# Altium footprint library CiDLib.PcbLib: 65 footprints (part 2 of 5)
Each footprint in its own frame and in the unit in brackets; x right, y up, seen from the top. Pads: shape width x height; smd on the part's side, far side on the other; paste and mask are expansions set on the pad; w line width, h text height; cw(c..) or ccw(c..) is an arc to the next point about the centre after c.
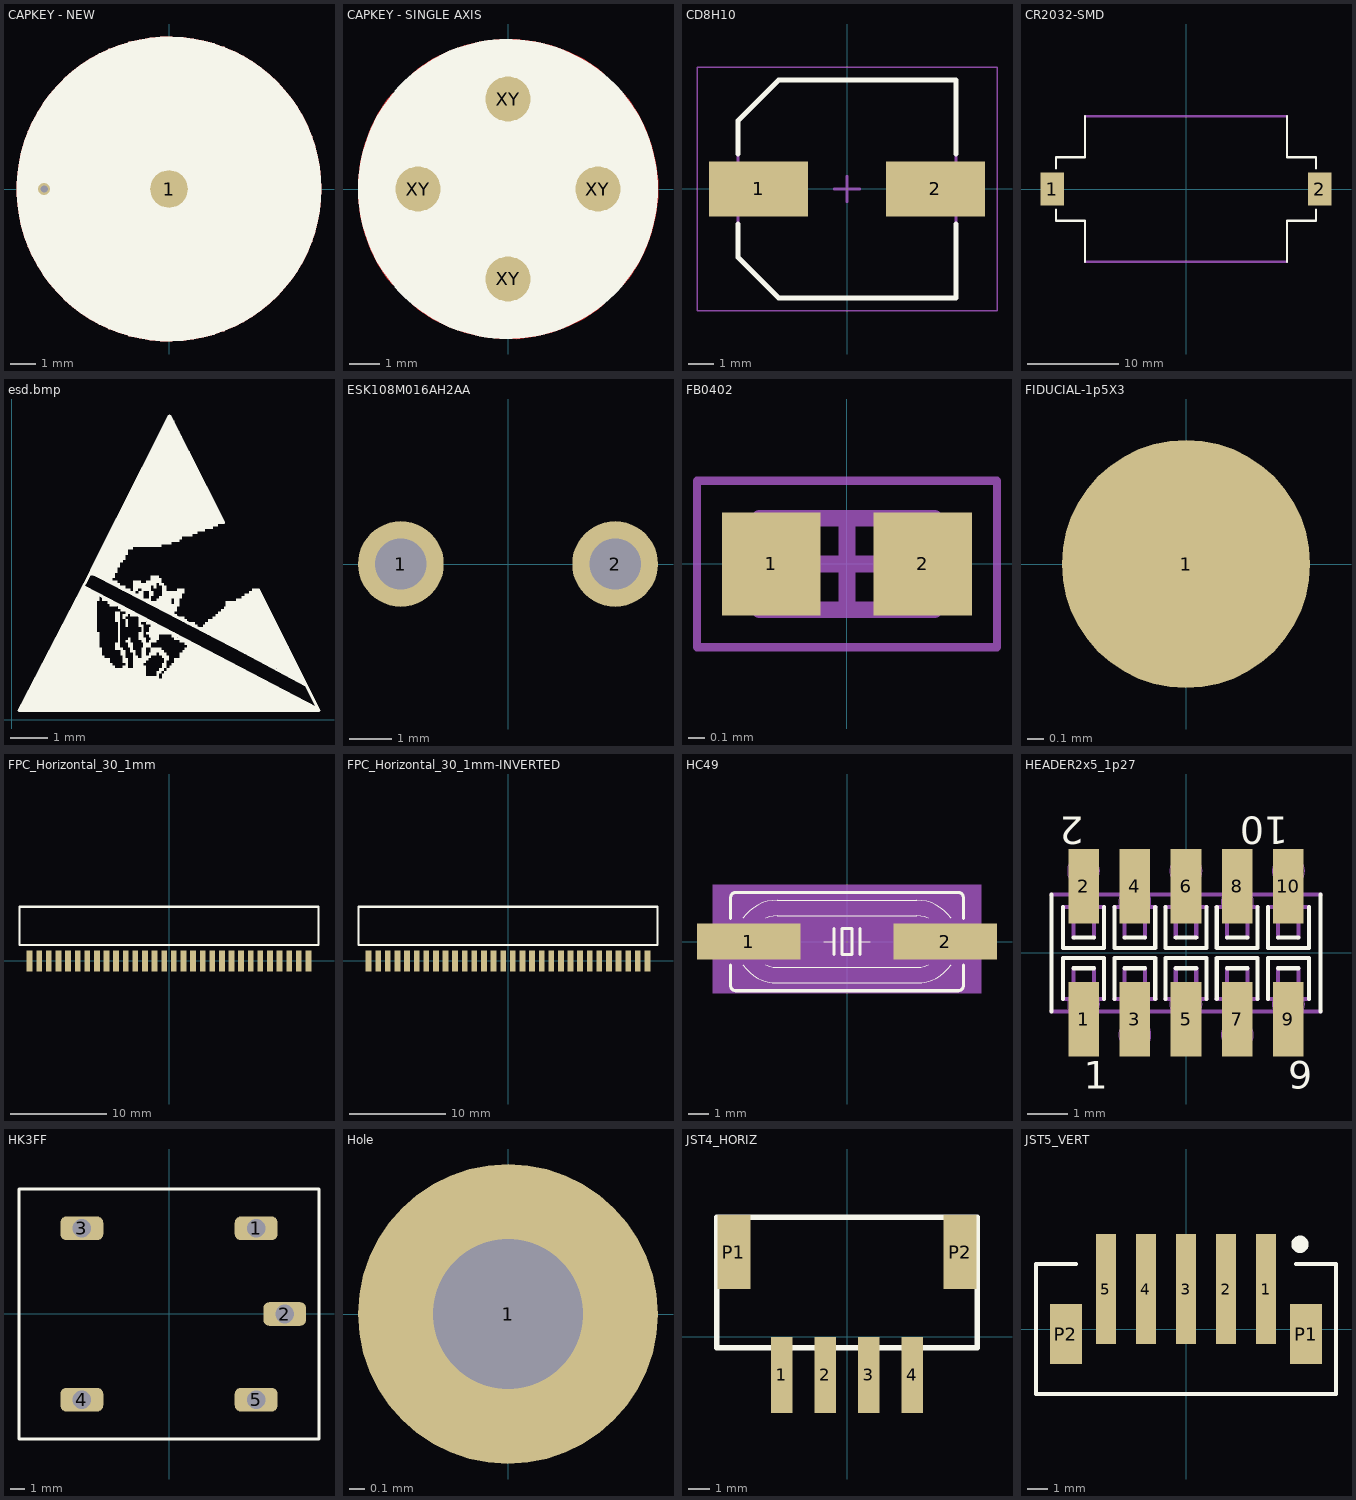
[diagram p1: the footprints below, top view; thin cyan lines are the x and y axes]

## CAPKEY - NEW [mm]
pads (1):
  round 1.5 smd paste-5 mask-2540: 1(0,0)
via -5,0 diameter 0.5 hole 0.3
Top Layer:
  circle w0.203: c0,0 r6
  region: 0,-6 -0.295,-6 -0.881,-5.942 -1.46,-5.827 -2.024,-5.656 -2.568,-5.43 -3.088,-5.153 -3.579,-4.825 -4.034,-4.451 -4.451,-4.034 -4.825,-3.579 -5.153,-3.088 -5.43,-2.568 -5.656,-2.024 -5.827,-1.46 -5.942,-0.881 -6,-0.295 -6,0 -6,0.295 -5.942,0.881 -5.827,1.46 -5.656,2.024 -5.43,2.568 -5.153,3.088 -4.825,3.579 -4.451,4.034 -4.034,4.451 -3.579,4.825 -3.088,5.153 -2.568,5.43 -2.024,5.656 -1.46,5.827 -0.881,5.942 -0.295,6 0,6 0.295,6 0.881,5.942 1.46,5.827 2.024,5.656 2.568,5.43 3.088,5.153 3.579,4.825 4.034,4.451 4.451,4.034 4.825,3.579 5.153,3.088 5.43,2.568 5.656,2.024 5.827,1.46 5.942,0.881 6,0.295 6,0 6,-0.295 5.942,-0.881 5.827,-1.46 5.656,-2.024 5.43,-2.568 5.153,-3.088 4.825,-3.579 4.451,-4.034 4.034,-4.451 3.579,-4.825 3.088,-5.153 2.568,-5.43 2.024,-5.656 1.46,-5.827 0.881,-5.942 0.295,-6
Top Overlay:
  circle w0.203: c0,0 r6
  region: 0,-6 -0.295,-6 -0.881,-5.942 -1.46,-5.827 -2.024,-5.656 -2.568,-5.43 -3.088,-5.153 -3.579,-4.825 -4.034,-4.451 -4.451,-4.034 -4.825,-3.579 -5.153,-3.088 -5.43,-2.568 -5.656,-2.024 -5.827,-1.46 -5.942,-0.881 -6,-0.295 -6,0 -6,0.295 -5.942,0.881 -5.827,1.46 -5.656,2.024 -5.43,2.568 -5.153,3.088 -4.825,3.579 -4.451,4.034 -4.034,4.451 -3.579,4.825 -3.088,5.153 -2.568,5.43 -2.024,5.656 -1.46,5.827 -0.881,5.942 -0.295,6 0,6 0.295,6 0.881,5.942 1.46,5.827 2.024,5.656 2.568,5.43 3.088,5.153 3.579,4.825 4.034,4.451 4.451,4.034 4.825,3.579 5.153,3.088 5.43,2.568 5.656,2.024 5.827,1.46 5.942,0.881 6,0.295 6,0 6,-0.295 5.942,-0.881 5.827,-1.46 5.656,-2.024 5.43,-2.568 5.153,-3.088 4.825,-3.579 4.451,-4.034 4.034,-4.451 3.579,-4.825 3.088,-5.153 2.568,-5.43 2.024,-5.656 1.46,-5.827 0.881,-5.942 0.295,-6

## CAPKEY - SINGLE AXIS [mm]
pads (4):
  round 1.5 smd paste-5 mask-2540: XY(-3,0) XY(0,-3) XY(0,3) XY(3,0)
Top Layer:
  region: -3.83,-3.214 -4.017,-2.991 -4.337,-2.504 -4.599,-1.984 -4.798,-1.436 -4.932,-0.87 -5,-0.291 -5,0.291 -4.932,0.87 -4.798,1.436 -4.599,1.984 -4.337,2.504 -4.017,2.991 -3.83,3.214 -0.5,0
  region: -3.214,-3.83 0,-0.5 3.214,-3.83 2.991,-4.017 2.504,-4.337 1.984,-4.599 1.436,-4.798 0.87,-4.932 0.291,-5 -0.291,-5 -0.87,-4.932 -1.436,-4.798 -1.984,-4.599 -2.504,-4.337 -2.991,-4.017
  region: 0,0.5 -3.214,3.83 -2.991,4.017 -2.504,4.337 -1.984,4.599 -1.436,4.798 -0.87,4.932 -0.291,5 0.291,5 0.87,4.932 1.436,4.798 1.984,4.599 2.504,4.337 2.991,4.017 3.214,3.83
  region: 0.5,0 3.83,3.214 4.017,2.991 4.337,2.504 4.599,1.984 4.798,1.436 4.932,0.87 5,0.291 5,-0.291 4.932,-0.87 4.798,-1.436 4.599,-1.984 4.337,-2.504 4.017,-2.991 3.83,-3.214
  lines w0.203: -3,0 3,0 ; 0,-3 0,3
Top Overlay:
  circle w6: c0,0 r2

## CD8H10 [mm] "Aluminum Electrolytic Capacitor, Body 8,30x8,30x10,50mm, IPC Medium Density"
height 10.5
pads (2):
  rect 3.85x2.15 smd: 1(-3.45,0) 2(3.45,0)
Top Overlay:
  lines w0.2: -4.25,-1.375 -4.25,-2.663 -2.663,-4.25 4.25,-4.25 4.25,-1.375 ; -4.25,1.375 -4.25,2.662 -2.663,4.25 4.25,4.25 4.25,1.375
Mechanical 13:
  lines w0.1: -4.25,-2.663 -4.25,2.662 -2.663,4.25 4.25,4.25 4.25,-4.25 -2.663,-4.25 -4.25,-2.663
Mechanical 15:
  lines w0.05: -5.85,-4.75 5.85,-4.75 5.85,4.75 -5.85,4.75 -5.85,-4.75
  lines w0.1: -0.5,0 0.5,0 ; 0,-0.5 0,0.5
3D body: height 10.5, standoff 0, extent -4.25,-4.25 4.25,4.247
3D body: height 3.5, standoff 0, extent -4.25,-4.25 4.25,4.25

## CR2032-SMD [mm] "CR2032 Battery holder (SMD)"
pads (2):
  rect 2.6x3.6 smd: 1(-14.7,0) 2(14.7,0)
Top Overlay:
  lines w0.254: -14.3,-2.25 -14.3,-3.5 -11.1,-3.5 -11.1,-8 ; -14.3,2.25 -14.3,3.5 -11.1,3.5 -11.1,8 ; 11.1,-8 11.1,-3.5 14.3,-3.5 14.3,-2.25 ; 11.1,8 11.1,3.5 14.3,3.5 14.3,2.25
Mechanical 16:
  lines w0.254: -11.1,-8 11.1,-8 ; -11.1,8 11.1,8
3D body: height 5.55, standoff 0, extent -16,-8 16,8

## esd.bmp [mm]
height 1.1
Top Overlay:
  drawing of 316 lines, arcs and shapes, not listed

## ESK108M016AH2AA [mm] "CAP ALUM 1000UF 20% 16V RADIAL"
pads (2):
  round 2 hole 1.2: 1(-2.5,0) 2(2.5,0)

## FB0402 [mm]
height 0.5
pads (2):
  rect 0.59x0.62 smd: 1(-0.455,0) 2(0.455,0)
Mechanical 13:
  lines w0.1: -0.525,-0.275 0.525,-0.275 0.525,0.275 -0.525,0.275 -0.525,-0.275
Mechanical 15:
  lines w0.05: -0.9,-0.5 0.9,-0.5 0.9,0.5 -0.9,0.5 -0.9,-0.5
  lines w0.1: -0.275,0 0.275,0 ; 0,-0.275 0,0.275
3D body: height 0.5, standoff 0, extent 0.275,-0.275 0.525,0.275
3D body: height 0.5, standoff 0, extent -0.525,-0.275 -0.275,0.275
3D body: height 0.5, standoff 0, extent -0.275,-0.275 0.275,0.275

## FIDUCIAL-1p5X3 [mm]
pads (1):
  rrect100% 1.5x1.5 smd: 1(0,0)
Top Solder:
  circle w1.27: c0,0 r0.906

## FPC_Horizontal_30_1mm [mm] "Horizontal FPC connector with 30 leads and 1mm pitch"
pads (30):
  rect 0.6x2.2 smd: 1(-14.5,0) 2(-13.5,0) 3(-12.5,0) 4(-11.5,0) 5(-10.5,0) 6(-9.5,0) 7(-8.5,0) 8(-7.5,0) 9(-6.5,0) 10(-5.5,0) 11(-4.5,0) 12(-3.5,0) 13(-2.5,0) 14(-1.5,0) 15(-0.5,0) 16(0.5,0) 17(1.5,0) 18(2.5,0) 19(3.5,0) 20(4.5,0) 21(5.5,0) 22(6.5,0) 23(7.5,0) 24(8.5,0) 25(9.5,0) 26(10.5,0) 27(11.5,0) 28(12.5,0) 29(13.5,0) 30(14.5,0)
Top Overlay:
  lines w0.254: -15.55,1.65 15.55,1.65 15.55,5.65 -15.55,5.65 -15.55,1.65
3D body: height 3, standoff 0, extent -15.549,1.651 15.549,5.649

## FPC_Horizontal_30_1mm-INVERTED [mm] "Horizontal FPC connector with 30 leads and 1mm pitch"
pads (30):
  rect 0.6x2.2 smd: 1(14.5,0) 2(13.5,0) 3(12.5,0) 4(11.5,0) 5(10.5,0) 6(9.5,0) 7(8.5,0) 8(7.5,0) 9(6.5,0) 10(5.5,0) 11(4.5,0) 12(3.5,0) 13(2.5,0) 14(1.5,0) 15(0.5,0) 16(-0.5,0) 17(-1.5,0) 18(-2.5,0) 19(-3.5,0) 20(-4.5,0) 21(-5.5,0) 22(-6.5,0) 23(-7.5,0) 24(-8.5,0) 25(-9.5,0) 26(-10.5,0) 27(-11.5,0) 28(-12.5,0) 29(-13.5,0) 30(-14.5,0)
Top Overlay:
  lines w0.254: -15.55,1.65 -15.55,5.65 15.55,5.65 15.55,1.65 -15.55,1.65
3D body: height 3, standoff 0, extent -15.549,1.651 15.549,5.649

## HC49 [mil]
pads (2):
  rect 200x70 smd: 1(-190,0) 2(190,0)
Top Overlay:
  lines w2: -201.15,-45 ccw(c-135,0) -135,-80 135,-80 ccw(c135,0) 201.14,-45 ; -201.15,45 cw(c-135,-0.01) -135,80 135,80 cw(c135,0) 201.15,45 ; -156.8,-45 ccw(c-135,0.01) -135,-50 135,-50 ccw(c135,0.01) 156.8,-45 ; -156.8,45 cw(c-135,-0.01) -135,50 135,50 cw(c135,-0.01) 156.8,45 ; -45,0 -25,0 ; 25,0 45,0
  lines w6: -225,-45 -225,-85 ccw(c-215,-85) -215,-95 215,-95 ccw(c215,-85) 225,-85 225,-45 ; -225,45 -225,85 cw(c-215,85) -215,95 215,95 cw(c215,85) 225,85 225,45 ; -25,-25 -25,0 -25,25 ; 25,-25 25,0 25,25 ; -10,-25 10,-25 10,25 -10,25 -10,-25
Mechanical 10:
  rectangle: -260,-100 260,110
Mechanical 16:
  lines w2: -201.15,-45 cw(c-135,0) -201.15,45 ; -156.8,-45 cw(c-135,0) -156.8,45 ; 156.8,-45 ccw(c135,0) 156.8,45 ; 201.15,-45 ccw(c135,0) 201.15,45
  lines w6: -225,-45 -225,45 ; -225,-15 -255,-15 -255,15 -225,15 ; 225,-45 225,-15 ; 225,45 225,15 ; 225,-15 255,-15 255,15 225,15 ; 225,-15 225,15

## HEADER2x5_1p27 [mm] "HEADER2x5 1.27"
pads (10):
  rect 0.76x1.85 smd: 1(-2.54,-1.65) 2(-2.54,1.65) 3(-1.27,-1.65) 4(-1.27,1.65) 5(0,-1.65) 6(0,1.65) 7(1.27,-1.65) 8(1.27,1.65) 9(2.54,-1.65) 10(2.54,1.65)
Top Overlay:
  lines w0.102: -3.335,-1.45 -3.335,1.45 ; -3.048,-1.143 -3.048,-0.127 -2.032,-0.127 -2.032,-1.143 ; -3.048,1.143 -3.048,0.127 -2.032,0.127 -2.032,1.143 ; -2.794,-0.381 -2.286,-0.381 ; -2.794,0.381 -2.286,0.381 ; -1.778,-1.143 -1.778,-0.127 -0.762,-0.127 -0.762,-1.143 ; -1.778,1.143 -1.778,0.127 -0.762,0.127 -0.762,1.143 ; -1.524,-0.381 -1.016,-0.381 ; -1.524,0.381 -1.016,0.381 ; -0.508,-1.143 -0.508,-0.127 0.508,-0.127 0.508,-1.143 ; -0.508,1.143 -0.508,0.127 0.508,0.127 0.508,1.143 ; -0.254,-0.381 0.254,-0.381 ; -0.254,0.381 0.254,0.381 ; 0.762,-1.143 0.762,-0.127 1.778,-0.127 1.778,-1.143 ; 0.762,1.143 0.762,0.127 1.778,0.127 1.778,1.143 ; 1.016,-0.381 1.524,-0.381 ; 1.016,0.381 1.524,0.381 ; 2.032,-1.143 2.032,-0.127 3.048,-0.127 3.048,-1.143 ; 2.032,1.143 2.032,0.127 3.048,0.127 3.048,1.143 ; 2.286,-0.381 2.794,-0.381 ; 2.286,0.381 2.794,0.381 ; 3.335,-1.45 3.335,1.45
  text "1" at -2.54,-3.375 h0.69
  text "2" at -2.54,3.375 h0.69
  text "9" at 2.54,-3.375 h0.69
  text "10" at 2.54,3.375 h0.69
Mechanical 16:
  lines w0.102: -3.335,-1.45 3.335,-1.45 ; -3.335,1.45 3.335,1.45 ; -3.048,-1.143 -2.032,-1.143 ; -3.048,1.143 -2.032,1.143 ; -2.794,-0.381 -2.794,-0.889 -2.286,-0.889 -2.286,-0.381 ; -2.794,0.381 -2.794,0.889 -2.286,0.889 -2.286,0.381 ; -1.778,-1.143 -0.762,-1.143 ; -1.778,1.143 -0.762,1.143 ; -1.524,-0.381 -1.524,-0.889 -1.016,-0.889 -1.016,-0.381 ; -1.524,0.381 -1.524,0.889 -1.016,0.889 -1.016,0.381 ; -0.508,-1.143 0.508,-1.143 ; -0.508,1.143 0.508,1.143 ; -0.254,-0.381 -0.254,-0.889 0.254,-0.889 0.254,-0.381 ; -0.254,0.381 -0.254,0.889 0.254,0.889 0.254,0.381 ; 0.762,-1.143 1.778,-1.143 ; 0.762,1.143 1.778,1.143 ; 1.016,-0.381 1.016,-0.889 1.524,-0.889 1.524,-0.381 ; 1.016,0.381 1.016,0.889 1.524,0.889 1.524,0.381 ; 2.032,-1.143 3.048,-1.143 ; 2.032,1.143 3.048,1.143 ; 2.286,-0.381 2.286,-0.889 2.794,-0.889 2.794,-0.381 ; 2.286,0.381 2.286,0.889 2.794,0.889 2.794,0.381
Mechanical 86:
  circle w0: c-2.54,2.032 r0.4
  circle w0: c-1.27,1.27 r0.4
  circle w0: c0,2.032 r0.4
  circle w0: c1.27,1.27 r0.4
  circle w0: c2.54,2.032 r0.4
  circle w0: c-2.54,-1.27 r0.4
  circle w0: c-1.27,-2.032 r0.4
  circle w0: c0,-1.27 r0.4
  circle w0: c1.27,-2.032 r0.4
  circle w0: c2.54,-1.27 r0.4

## HK3FF [mm]
pads (5):
  rrect50% 3x1.65 hole 1.3: 1(6.1,6) 2(8.1,0) 3(-6.1,6) 4(-6.1,-6) 5(6.1,-6)
Top Overlay:
  lines w0.203: -10.5,-8.75 10.5,-8.75 10.5,-7.25 10.5,8.75 -10.5,8.75 -10.5,-8.75
3D body: height 15.8, standoff 0, extent -9.5,-7.75 9.5,7.75

## Hole [mm] "PTH Hole for wire soldering"
pads (1):
  round 2 hole 1: 1(0,0)

## JST4_HORIZ [mm] "SMT Horizontal JST 4 leads connector"
pads (6):
  rect 1x3.5 smd: 1(-3,-1.75) 2(-1,-1.75) 3(1,-1.75) 4(3,-1.75)
  rect 1.5x3.4 smd: P1(-5.2,3.9) P2(5.2,3.9)
Top Overlay:
  lines w0.254: -6,-0.5 6,-0.5 6,5.5 -6,5.5 -6,-0.5
3D body: height 5.5, standoff 0, extent -5.999,-0.499 5.999,5.499

## JST5_VERT [mm]
pads (7):
  rect 1x5.5 smd: 1(4,2) 2(2,2) 3(0,2) 4(-2,2) 5(-4,2)
  rect 1.6x3 smd: P1(6,-0.25) P2(-6,-0.25)
Top Overlay:
  circle w0.508: c5.7,4.235 r0.18
  lines w0.203: -5.5,3.25 -7.5,3.25 -7.5,-3.25 7.5,-3.25 7.5,3.25 5.5,3.25
3D body: height 6, standoff 0, extent -7,-2.75 7,2.75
